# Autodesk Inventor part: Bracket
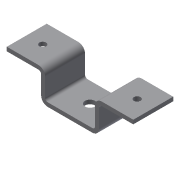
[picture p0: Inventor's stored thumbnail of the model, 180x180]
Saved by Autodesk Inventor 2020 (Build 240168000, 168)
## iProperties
Part Number: Bracket
Document SubType Name: Modeling
Created: 2003-01
Designer: Owner
Density: 1 g/cm^3
Material: Generic
Appearance: Default
Control State: 0
Master: False
Checked Out: False
Shininess: 64.0
Length Units: 11269
Angle Units: 11279
Time Units: 11290
Mass Units: 11283
Length Display Precision: 3
Angle Display Precision: 2
Compacted: True
Density: 0.0
Volumn: 0.0
Area: 0.0
PropertySet Name: Model Information
Author: Owner
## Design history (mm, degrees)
node "Sketch1"
sketch "Sketch2"
  geometry: L1 (487.39, 112.858)-(199.89, 112.858); L2 (199.89, 112.858)-(199.89, -95.142); L3 (199.89, -95.142)-(-175.11, -95.142); L4 (-175.11, -95.142)-(-175.11, 112.858); L5 (-175.11, 112.858)-(-462.61, 112.858); L6 (-462.61, 82.858)-(-205.11, 82.858); L7 (-205.11, 82.858)-(-205.11, -125.142); L8 (-205.11, -125.142)-(229.89, -125.142); L9 (229.89, -125.142)-(229.89, 82.858); L10 (229.89, 82.858)-(487.39, 82.858); L11 (487.39, 112.858)-(487.39, 82.858); L12 (-462.61, 112.858)-(-462.61, 82.858)
  constraints: 24 end point, 5 parallel, 3 perpendicular, 2 collinear, 2 equal length, 1 horizontal, 4 other
  dimensions: "d0" = 375 distance between parallel lines of L4 L2; "d1" = 950 distance of L5.end L1.start; "d2" = 30 distance between parallel lines of L1 L10; "d3" = 238 distance between parallel lines of L5 L8
extrude "Extrusion1" new body sketch "Sketch2" stored distance "d4" = 300; taper "d5" = 0 deg
fillet "Fillet1" dims "d6" = 20
fillet "Fillet2" dims "d7" = 50
sketch "Sketch3"
  geometry: L1 (237.5, 300)-(0, 300) reference; L2 (0, 300)-(0, 0) reference; 1 further point
  dimensions: "d8" = 120 distance from line of L2 point (120, 150); "d9" = 150 distance from line of L1 point (120, 150)
hole "Hole1" sketch "Sketch3" at (120, 150) diameter "d10" = 50; stored, may be unused: countersink angle "d14" = 82 deg, drill point angle "d16" = 118 deg; dims "d11" = 6, "d12" = 4, "d13" = 2, "d15" = 8
pattern_linear "Rectangular Pattern1" dims "d19" = 710
sketch "Sketch4"
  geometry: L1 (0, -300)-(335, -300) reference; 1 further point
  dimensions: "d20" = 150 distance from line of L1 point (167.5, -150)
hole "Hole2" sketch "Sketch4" at (167.5, -150) diameter "d21" = 75; stored, may be unused: countersink angle "d25" = 82 deg, drill point angle "d27" = 118 deg; dims "d22" = 6, "d23" = 4, "d24" = 2, "d26" = 8
body "Solid1"
